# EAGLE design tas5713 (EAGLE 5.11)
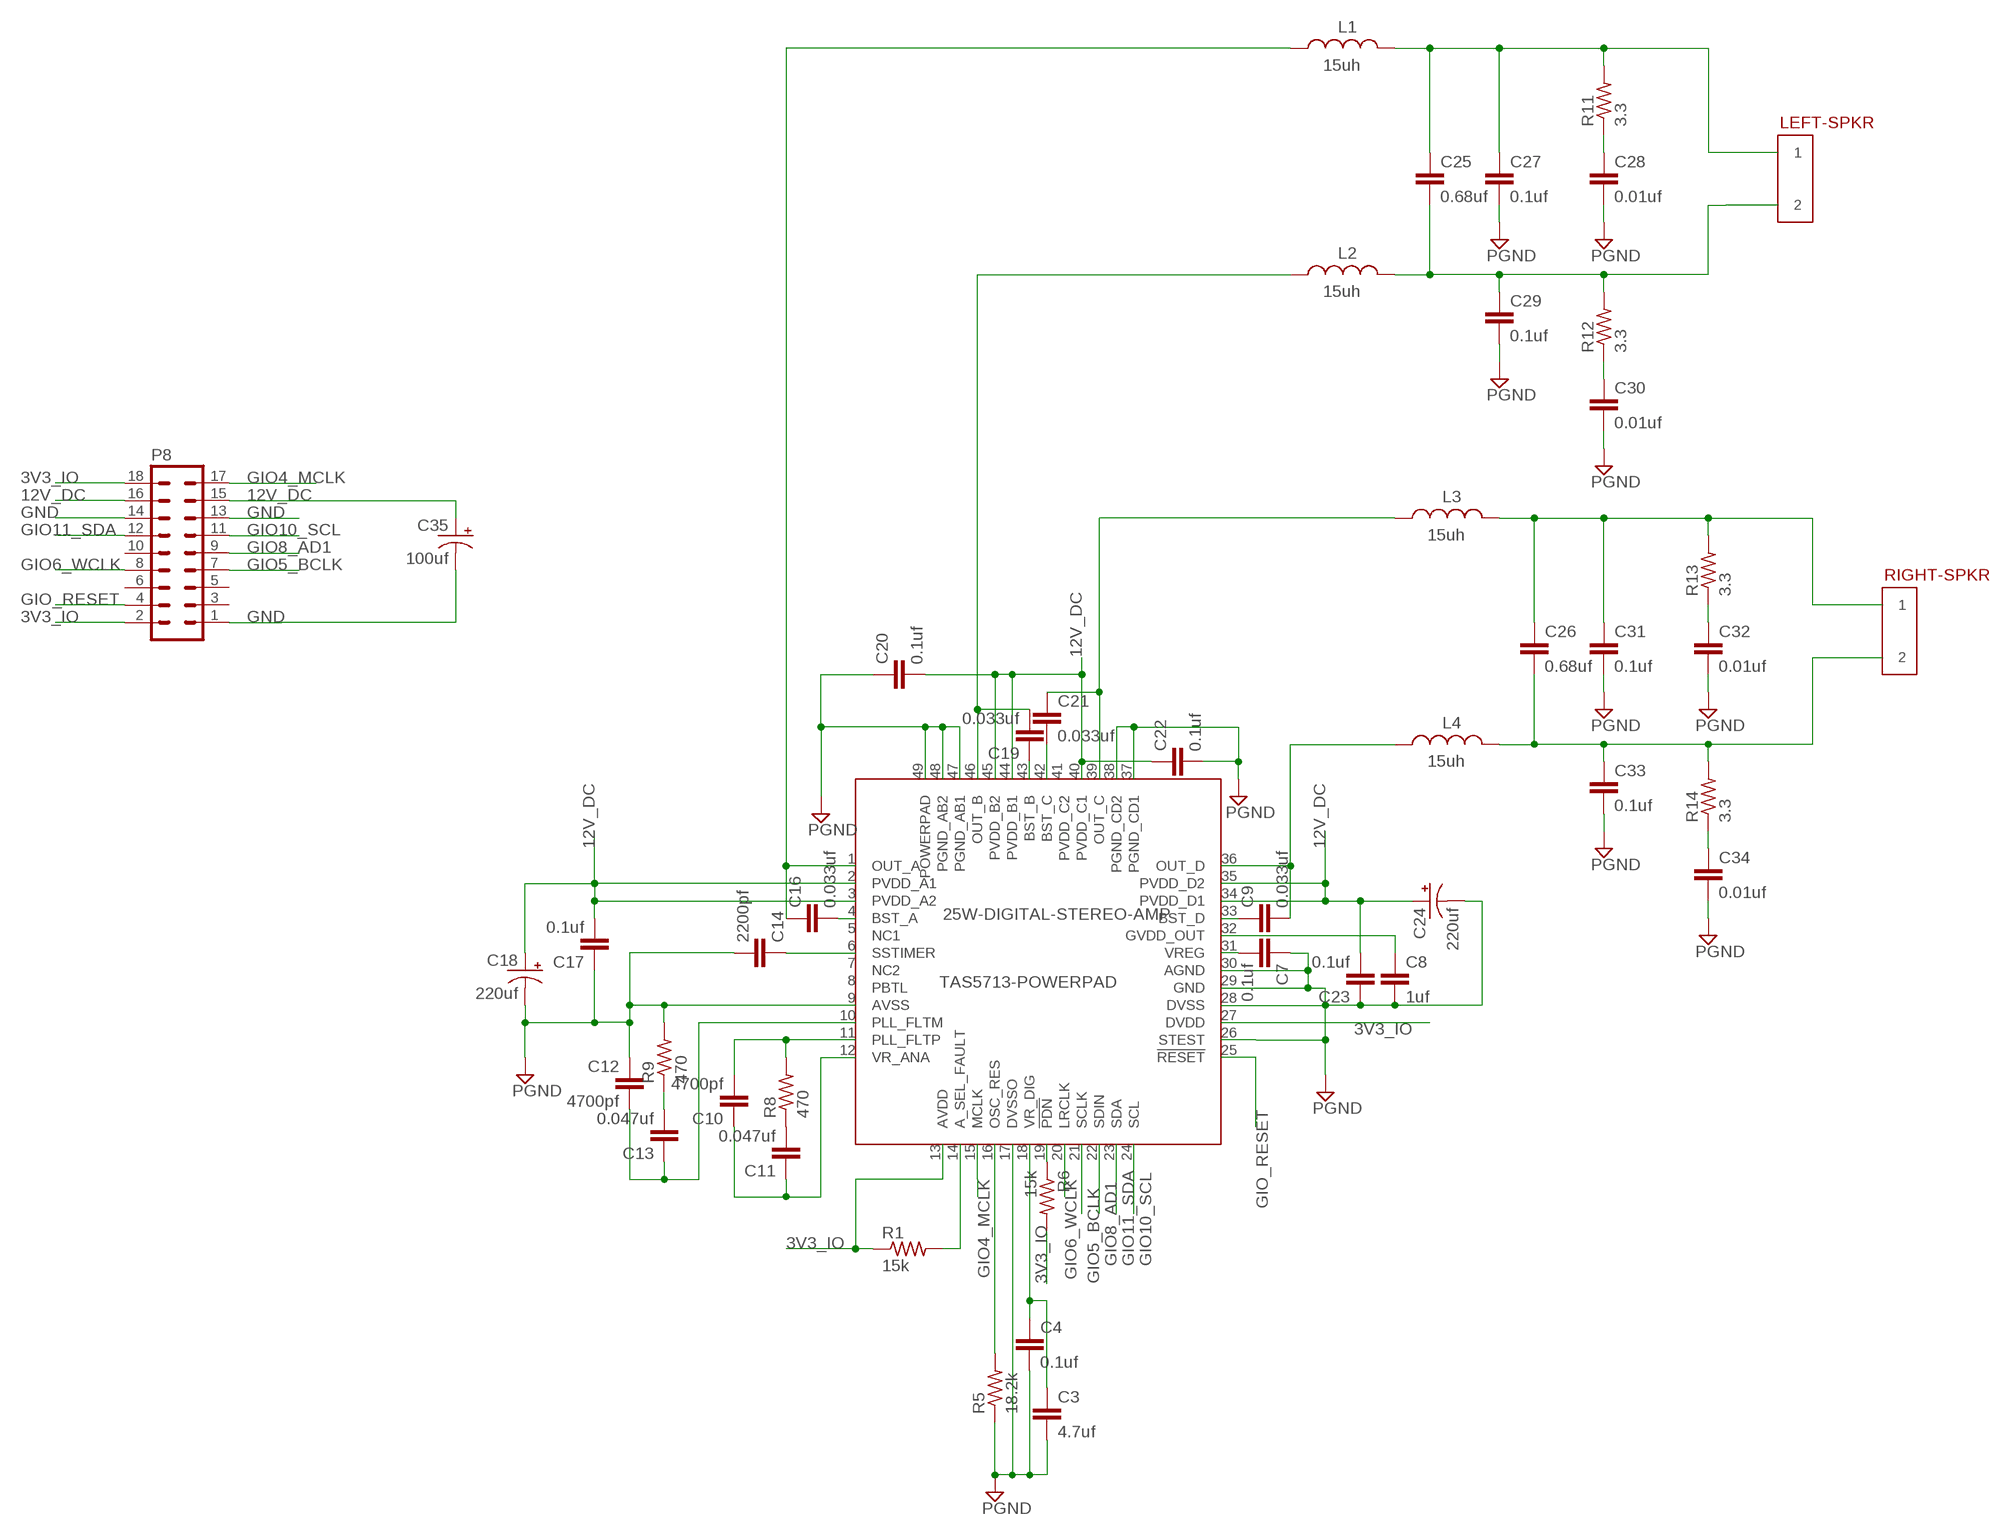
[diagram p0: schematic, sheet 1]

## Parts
25W-DIGITAL-STEREO-AMP  TAS5713-POWERPAD  [SCHMARTBOARD-VQFN48-POWERPAD]
C3  4.7uf  C-EUC1206  [C1206]
C4  0.1uf  C-EUC1206  [C1206]
C7  0.1uf  C-EUC1206  [C1206]
C8  1uf  C-EUC1206  [C1206]
C9  0.033uf  C-EUC1206  [C1206]
C10  4700pf  C-EUC1206  [C1206]
C11  0.047uf  C-EUC1206  [C1206]
C12  4700pf  C-EUC1206  [C1206]
C13  0.047uf  C-EUC1206  [C1206]
C14  2200pf  C-EUC1206  [C1206]
C16  0.033uf  C-EUC1206  [C1206]
C17  0.1uf  C-EUC1206  [C1206]
C18  220uf  CPOL-US175TMP-0808  [175TMP-0808]
C19  0.033uf  C-EUC1206  [C1206]
C20  0.1uf  C-EUC1206  [C1206]
C21  0.033uf  C-EUC1206  [C1206]
C22  0.1uf  C-EUC1206  [C1206]
C23  0.1uf  C-EUC1206  [C1206]
C24  220uf  CPOL-US175TMP-0808  [175TMP-0808]
C25  0.68uf  C-EUC1206  [C1206]
C26  0.68uf  C-EUC1206  [C1206]
C27  0.1uf  C-EUC1206  [C1206]
C28  0.01uf  C-EUC1206  [C1206]
C29  0.1uf  C-EUC1206  [C1206]
C30  0.01uf  C-EUC1206  [C1206]
C31  0.1uf  C-EUC1206  [C1206]
C32  0.01uf  C-EUC1206  [C1206]
C33  0.1uf  C-EUC1206  [C1206]
C34  0.01uf  C-EUC1206  [C1206]
C35  100uf  CPOL-US175TMP-0808  [175TMP-0808]
L1  15uh  INDUCTOR-ABRACON-1306S  [INDUCTOR-ABRACON-1306S]
L2  15uh  INDUCTOR-ABRACON-1306S  [INDUCTOR-ABRACON-1306S]
L3  15uh  INDUCTOR-ABRACON-1306S  [INDUCTOR-ABRACON-1306S]
L4  15uh  INDUCTOR-ABRACON-1306S  [INDUCTOR-ABRACON-1306S]
LEFT-SPKR  SCREW-CLAMP-1.5  [SCREW-CLAMP-1.5]
P8  MA09-2  [MA09-2]
R1  15k  R-US_R1206  [R1206]
R5  18.2k  R-US_R1206  [R1206]
R6  15k  R-US_R1206  [R1206]
R8  470  R-US_R1206  [R1206]
R9  470  R-US_R1206  [R1206]
R11  3.3  R-US_R1206  [R1206]
R12  3.3  R-US_R1206  [R1206]
R13  3.3  R-US_R1206  [R1206]
R14  3.3  R-US_R1206  [R1206]
RIGHT-SPKR  SCREW-CLAMP-1.5  [SCREW-CLAMP-1.5]

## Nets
3V3_IO: 25W-DIGITAL-STEREO-AMP.13(AVDD) 25W-DIGITAL-STEREO-AMP.27(DVDD) P8.2 P8.18 R1.1 R6.2
12V_DC: 25W-DIGITAL-STEREO-AMP.2(PVDD_A1) 25W-DIGITAL-STEREO-AMP.3(PVDD_A2) 25W-DIGITAL-STEREO-AMP.34(PVDD_D1) 25W-DIGITAL-STEREO-AMP.35(PVDD_D2) 25W-DIGITAL-STEREO-AMP.40(PVDD_C1) 25W-DIGITAL-STEREO-AMP.44(PVDD_B1) 25W-DIGITAL-STEREO-AMP.45(PVDD_B2) C17.2 C18.+ C20.2 C22.1 C23.2 C24.+ C35.+ P8.15 P8.16
GIO4_MCLK: 25W-DIGITAL-STEREO-AMP.15(MCLK) P8.17
GIO5_BCLK: 25W-DIGITAL-STEREO-AMP.21(SCLK) P8.7
GIO6_WCLK: 25W-DIGITAL-STEREO-AMP.20(LRCLK) P8.8
GIO8_AD1: 25W-DIGITAL-STEREO-AMP.22(SDIN) P8.9
GIO10_SCL: 25W-DIGITAL-STEREO-AMP.24(SCL) P8.11
GIO11_SDA: 25W-DIGITAL-STEREO-AMP.23(SDA) P8.12
GIO_RESET: 25W-DIGITAL-STEREO-AMP.25(!RESET) P8.4
GND: 25W-DIGITAL-STEREO-AMP.9(AVSS) 25W-DIGITAL-STEREO-AMP.17(DVSSO) 25W-DIGITAL-STEREO-AMP.26(STEST) 25W-DIGITAL-STEREO-AMP.28(DVSS) 25W-DIGITAL-STEREO-AMP.29(GND) 25W-DIGITAL-STEREO-AMP.30(AGND) 25W-DIGITAL-STEREO-AMP.37(PGND_CD1) 25W-DIGITAL-STEREO-AMP.38(PGND_CD2) 25W-DIGITAL-STEREO-AMP.47(PGND_AB1) 25W-DIGITAL-STEREO-AMP.48(PGND_AB2) 25W-DIGITAL-STEREO-AMP.49(POWERPAD) C3.2 C4.2 C7.1 C8.2 C12.1 C14.2 C17.1 C18.- C20.1 C22.2 C23.1 C24.- C27.2 C28.2 C29.2 C30.2 C31.2 C32.2 C33.2 C34.2 C35.- P8.1 P8.13 P8.14 R5.1 R9.2 ; supply symbol labelled PGND
N$1: 25W-DIGITAL-STEREO-AMP.4(BST_A) C16.2
N$2: 25W-DIGITAL-STEREO-AMP.1(OUT_A) C16.1 L1.1
N$3: 25W-DIGITAL-STEREO-AMP.43(BST_B) C19.1
N$4: 25W-DIGITAL-STEREO-AMP.46(OUT_B) C19.2 L2.1
N$5: 25W-DIGITAL-STEREO-AMP.42(BST_C) C21.2
N$6: 25W-DIGITAL-STEREO-AMP.14(A_SEL_FAULT) R1.2
N$7: 25W-DIGITAL-STEREO-AMP.33(BST_D) C9.1
N$8: 25W-DIGITAL-STEREO-AMP.36(OUT_D) C9.2 L4.1
N$9: 25W-DIGITAL-STEREO-AMP.31(VREG) C7.2
N$10: 25W-DIGITAL-STEREO-AMP.32(GVDD_OUT) C8.1
N$11: 25W-DIGITAL-STEREO-AMP.6(SSTIMER) C14.1
N$12: C28.1 R11.1
N$13: C25.2 C29.1 L2.2 LEFT-SPKR.2 R12.2
N$14: C30.1 R12.1
N$15: 25W-DIGITAL-STEREO-AMP.39(OUT_C) C21.1 L3.1
N$16: 25W-DIGITAL-STEREO-AMP.18(VR_DIG) C3.1 C4.1
N$17: 25W-DIGITAL-STEREO-AMP.16(OSC_RES) R5.2
N$18: C26.1 C31.1 L3.2 R13.2 RIGHT-SPKR.1
N$19: C25.1 C27.1 L1.2 LEFT-SPKR.1 R11.2
N$20: C32.1 R13.1
N$21: C26.2 C33.1 L4.2 R14.2 RIGHT-SPKR.2
N$22: C34.1 R14.1
N$23: 25W-DIGITAL-STEREO-AMP.19(!PDN) R6.1
N$24: 25W-DIGITAL-STEREO-AMP.10(PLL_FLTM) C12.2 C13.1
N$25: 25W-DIGITAL-STEREO-AMP.11(PLL_FLTP) C10.2 R8.2
N$26: 25W-DIGITAL-STEREO-AMP.12(VR_ANA) C10.1 C11.1
N$27: C11.2 R8.1
N$28: C13.2 R9.1
Unconnected: 25W-DIGITAL-STEREO-AMP.5(NC1) 25W-DIGITAL-STEREO-AMP.7(NC2) 25W-DIGITAL-STEREO-AMP.8(PBTL) 25W-DIGITAL-STEREO-AMP.41(PVDD_C2) P8.3 P8.5 P8.6 P8.10

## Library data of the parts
25W-DIGITAL-STEREO-AMP = trl:TAS5713-POWERPAD
C3 C4 C7-C14 C16 C17 C19-C23 C25-C34 = rcl:C-EU: CAPACITOR, European symbol
C18 C24 C35 = resistor:CPOL-US: POLARIZED CAPACITOR, American symbol
L1-L4 = trl:INDUCTOR-ABRACON-1306S
LEFT-SPKR RIGHT-SPKR = trl:SCREW-CLAMP-1.5
P8 = con-lstb:MA09-2: PIN HEADER
R1 R5 R6 R8 R9 R11-R14 = resistor:R-US_: RESISTOR, American symbol

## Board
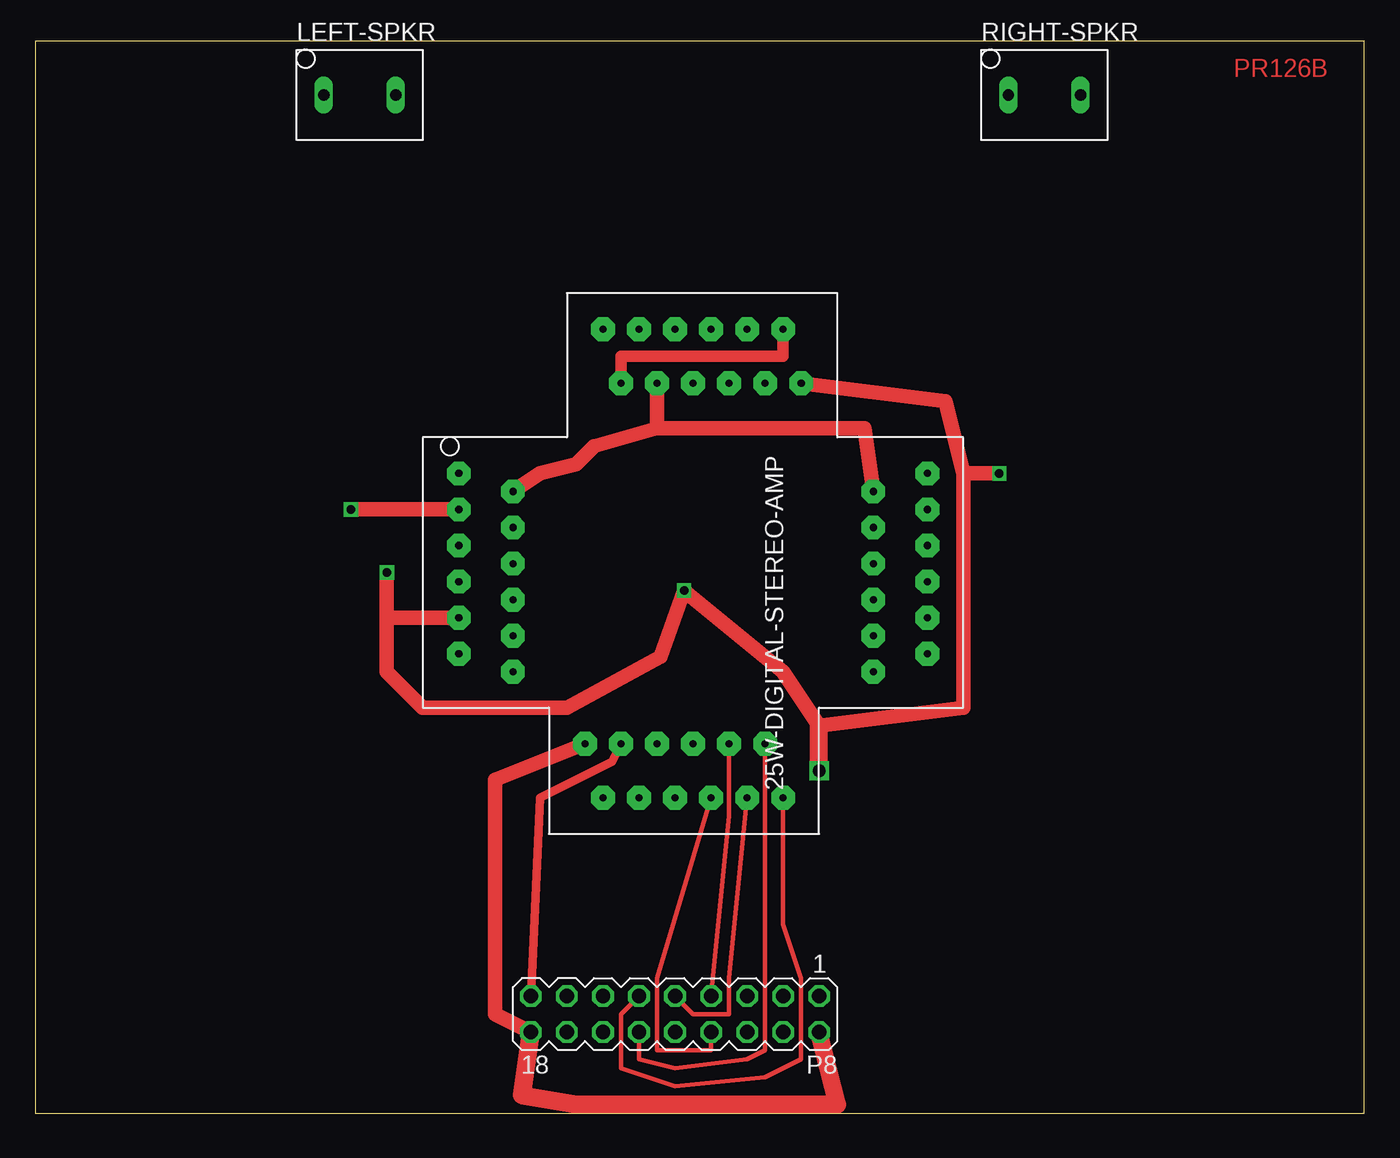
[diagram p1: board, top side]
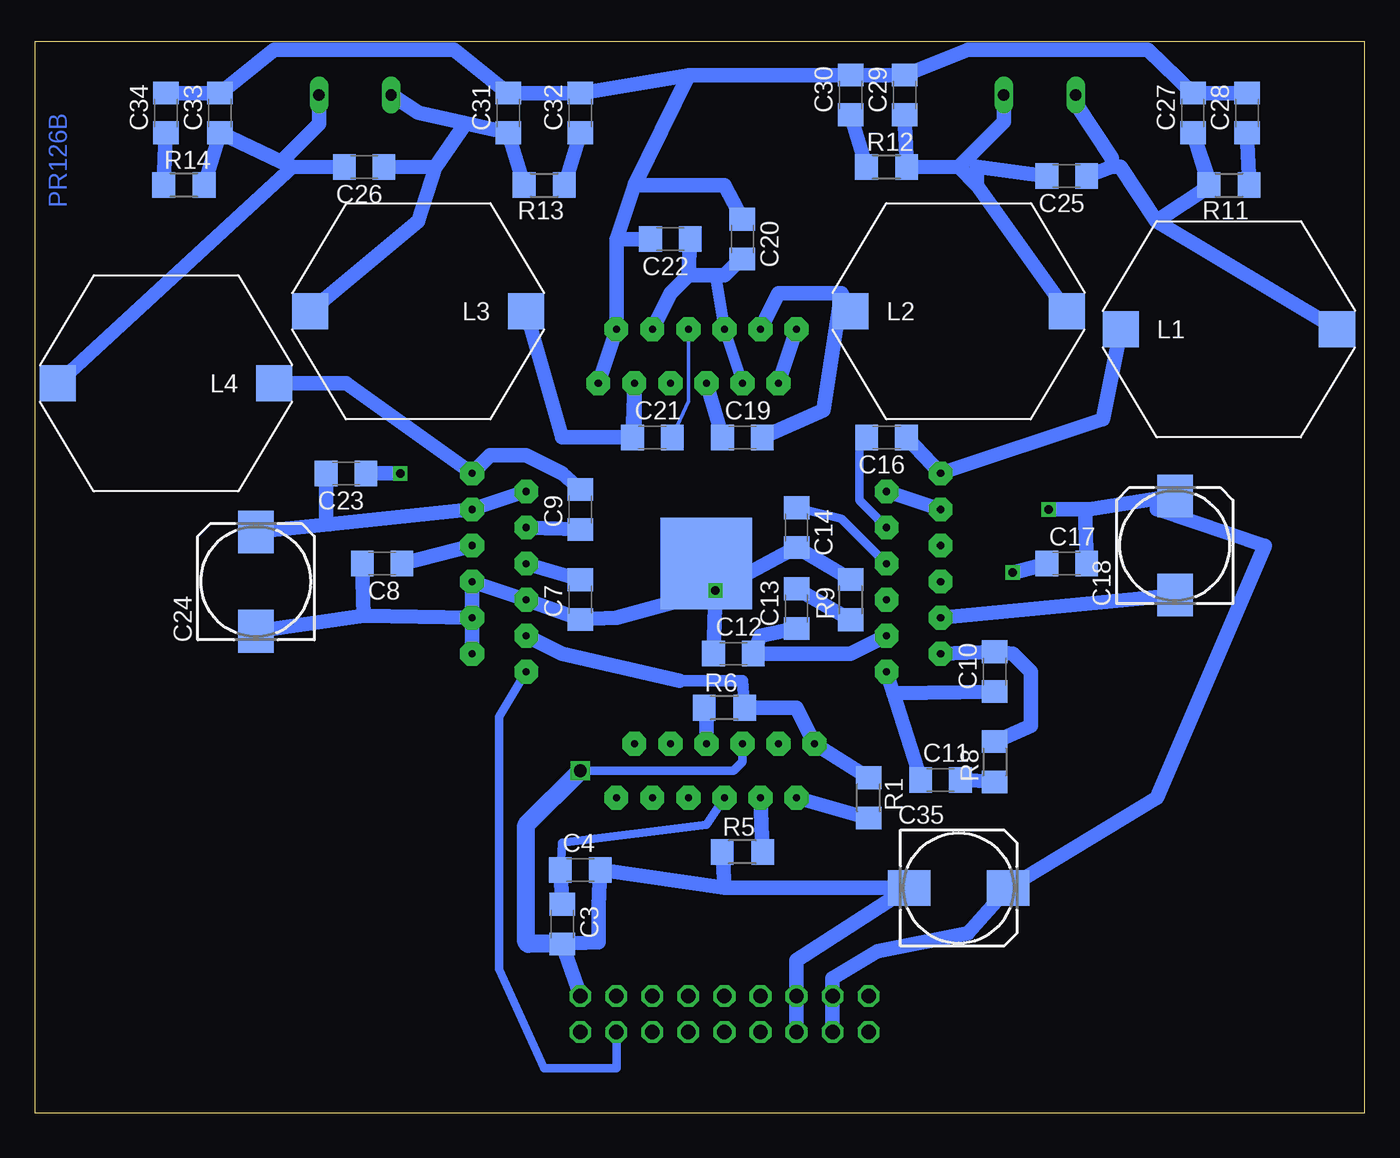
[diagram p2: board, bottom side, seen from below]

Size 93.65 x 75.56 mm. Coordinates in mm from the lower left corner, seen from the top.
Outline: 0,0 93.65,0 93.65,75.56 0,75.56 0,0
Copper layers (1*16): Top 0.035mm / dielectric 1.5mm / Bottom 0.035mm
Design rules "default": minimum track width 10mil, minimum drill 24mil, track to track 8mil, track to pad 8mil, pad to pad 8mil, via to via 8mil, smd to smd 8mil, copper to edge 40mil, drill to drill 8mil, minimum pad ring 10mil, minimum via ring 8mil, stop-mask expansion 4mil, vias tented up to drill 0mil, thermal gap 10mil

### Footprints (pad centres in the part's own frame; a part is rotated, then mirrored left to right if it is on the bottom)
SCHMARTBOARD-VQFN48-POWERPAD = drill 0.5 pad 1.676 octagon: 1 -6.35,-16.51; 2 -5.08,-12.7; 3 -3.81,-16.51; 4 -2.54,-12.7; 5 -1.27,-16.51; 6 0,-12.7; 7 1.27,-16.51; 8 2.54,-12.7; 9 3.81,-16.51; 10 5.08,-12.7; 11 6.35,-16.51; 12 7.62,-12.7; 13 12.7,-7.62; 14 16.51,-6.35; 15 12.7,-5.08; 16 16.51,-3.81; 17 12.7,-2.54; 18 16.51,-1.27; 19 12.7,0; 20 16.51,1.27; 21 12.7,2.54; 22 16.51,3.81; 23 12.7,5.08; 24 16.51,6.35; 25 7.62,12.7; 26 6.35,16.51; 27 5.08,12.7; 28 3.81,16.51; 29 2.54,12.7; 30 1.27,16.51; 31 0,12.7; 32 -1.27,16.51; 33 -2.54,12.7; 34 -3.81,16.51; 35 -5.08,12.7; 36 -6.35,16.51; 37 -12.7,7.62; 38 -16.51,6.35; 39 -12.7,5.08; 40 -16.51,3.81; 41 -12.7,2.54; 42 -16.51,1.27; 43 -12.7,0; 44 -16.51,-1.27; 45 -12.7,-2.54; 46 -16.51,-3.81; 47 -12.7,-5.08; 48 -16.51,-6.35 | smd 6.452 x 6.452 bottom: 49 0,0
C1206 = smd 1.6 x 1.8: 1 -1.4,0; 2 1.4,0
175TMP-0808 = smd 3 x 2.5: + 3.5,0; - -3.5,0
INDUCTOR-ABRACON-1306S = smd 2.54 x 2.54: 1 0,0; 2 15.24,0
SCREW-CLAMP-1.5 = drill 0.8 long: 1 -1.27,0; 2 3.81,0
MA09-2 = drill 1.016 octagon: 1 -10.16,-1.27; 2 -10.16,1.27; 3 -7.62,-1.27; 4 -7.62,1.27; 5 -5.08,-1.27; 6 -5.08,1.27; 7 -2.54,-1.27; 8 -2.54,1.27; 9 0,-1.27; 10 0,1.27; 11 2.54,-1.27; 12 2.54,1.27; 13 5.08,-1.27; 14 5.08,1.27; 15 7.62,-1.27; 16 7.62,1.27; 17 10.16,-1.27; 18 10.16,1.27
R1206 = smd 1.6 x 1.803: 1 -1.422,0; 2 1.422,0

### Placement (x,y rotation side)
25W-DIGITAL-STEREO-AMP  46.35,38.73 270 top
C3  56.52,13.34 270 bottom
C4  55.24,17.14 0 bottom
C7  55.24,36.2 90 bottom
C8  69.22,38.73 180 bottom
C9  55.24,42.55 90 bottom
C10  26.04,31.11 90 bottom
C11  29.84,23.5 0 bottom
C12  44.45,32.38 0 bottom
C13  40.01,35.56 90 bottom
C14  40.01,41.27 270 bottom
C16  33.66,47.62 180 bottom
C17  20.95,38.73 0 bottom
C18  13.34,40.01 90 bottom
C19  43.81,47.62 0 bottom
C20  43.81,61.59 270 bottom
C21  50.16,47.62 0 bottom
C22  48.9,61.59 180 bottom
C23  71.75,45.09 180 bottom
C24  78.11,37.47 90 bottom
C25  20.95,66.04 180 bottom
C26  70.48,66.67 180 bottom
C27  12.06,70.48 90 bottom
C28  8.26,70.48 90 bottom
C29  32.38,71.75 90 bottom
C30  36.2,71.75 90 bottom
C31  60.33,70.48 90 bottom
C32  55.24,70.48 90 bottom
C33  80.64,70.48 90 bottom
C34  84.45,70.48 90 bottom
C35  28.57,15.88 0 bottom
L1  17.14,55.24 0 bottom
L2  36.2,56.52 0 bottom
L3  59.05,56.52 180 bottom
L4  76.83,51.44 180 bottom
LEFT-SPKR  21.59,71.75 0 top
P8  45.09,6.99 180 top
R1  34.92,22.23 270 bottom
R5  43.81,18.41 0 bottom
R6  45.09,28.57 0 bottom
R8  26.04,24.77 90 bottom
R9  36.2,36.2 90 bottom
R11  9.53,65.41 180 bottom
R12  33.66,66.67 0 bottom
R13  57.78,65.41 180 bottom
R14  83.19,65.41 0 bottom
RIGHT-SPKR  69.85,71.75 0 top

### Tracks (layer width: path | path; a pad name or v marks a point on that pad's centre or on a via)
3V3_IO
  Top 1.016: P8.18 32.38,6.99 32.38,23.5 25W-DIGITAL-STEREO-AMP.13
  Top 1.27: P8.2 56.52,0.64 38.1,0.64 34.29,1.27 P8.18
  Bottom 0.813: R6.2 43.81,30.48 48.26,30.48
  Bottom 1.016: 48.26,30.48 56.52,32.38 25W-DIGITAL-STEREO-AMP.27 | R1.1 25W-DIGITAL-STEREO-AMP.13 40.01,28.57 R6.2
12V_DC  (via drill 0.6)
  Top 1.016: 43.81,48.26 58.42,48.26 25W-DIGITAL-STEREO-AMP.35 | 25W-DIGITAL-STEREO-AMP.2 35.56,45.09 38.1,45.72 39.37,46.99 43.81,48.26 | v22.23,42.55 25W-DIGITAL-STEREO-AMP.3 | 43.81,48.26 25W-DIGITAL-STEREO-AMP.45
  Bottom 0.813: 25W-DIGITAL-STEREO-AMP.45 25W-DIGITAL-STEREO-AMP.44 45.72,59.05
  Bottom 1.016: 72.92,41.5 25W-DIGITAL-STEREO-AMP.34 25W-DIGITAL-STEREO-AMP.35 | 72.92,41.5 C24.+ | P8.16 P8.15 37.47,9.53 34.29,11.43 27.94,12.7 C35.+ 14.61,22.23 6.99,40.01 14.61,42.55 C18.+ 19.38,42.55 19.68,42.55 | 25W-DIGITAL-STEREO-AMP.3 25W-DIGITAL-STEREO-AMP.2 | 47.62,59.05 48.9,57.78 25W-DIGITAL-STEREO-AMP.40 | 47.62,59.05 45.72,59.05 45.09,59.05 43.95,60.2 C20.2 | 19.68,42.55 v22.23,42.55 | C23.2 73.16,41.74 72.92,41.5 | 19.68,42.55 C17.2 | 47.62,59.05 C22.1
GIO4_MCLK
  Top 0.61: P8.17 35.56,22.23 40.64,24.77 25W-DIGITAL-STEREO-AMP.15
GIO5_BCLK
  Top 0.305: P8.7 48.9,20.95 25W-DIGITAL-STEREO-AMP.21
GIO6_WCLK
  Top 0.305: P8.8 47.62,4.45 43.81,4.45 43.81,9.53 25W-DIGITAL-STEREO-AMP.20
GIO8_AD1
  Top 0.305: 25W-DIGITAL-STEREO-AMP.22 48.9,9.53 48.9,8.26 48.9,6.99 46.35,6.99 P8.9
GIO10_SCL
  Top 0.305: 25W-DIGITAL-STEREO-AMP.24 52.7,13.34 53.98,9.53 53.98,3.81 51.44,2.54 45.09,1.91 41.27,3.17 41.27,6.99 P8.11
GIO11_SDA
  Top 0.305: 25W-DIGITAL-STEREO-AMP.23 51.44,5.71 51.44,4.45 50.16,3.81 45.09,3.17 42.55,3.81 P8.12
GIO_RESET
  Bottom 0.61: P8.4 52.7,3.17 57.78,3.17 60.96,10.16 60.96,27.94 25W-DIGITAL-STEREO-AMP.25
GND  (via drill 0.6, 0.9)
  Top 0.813: 25W-DIGITAL-STEREO-AMP.47 41.27,53.34 52.7,53.34 25W-DIGITAL-STEREO-AMP.38
  Top 1.016: 25W-DIGITAL-STEREO-AMP.37 64.14,50.16 65.41,45.09 | 65.41,45.09 65.41,28.57 55.24,27.3 52.7,31.11 v45.72,36.83 44.05,32.17 37.47,28.57 27.3,28.57 24.77,31.11 24.77,34.92 | 65.41,45.09 v67.94,45.09 | 24.77,34.92 25W-DIGITAL-STEREO-AMP.9 | 24.77,34.92 v24.77,38.1
  Top 1.27: v55.24,24.13 55.24,27.3
  Bottom 0.61: 25W-DIGITAL-STEREO-AMP.17 43.81,24.77 44.45,24.13 v55.24,24.13
  Bottom 1.016: C28.2 C27.2 15.24,74.93 27.94,74.93 C29.2 C30.2 47.62,73.16 | C34.2 C33.2 76.83,74.93 64.14,74.93 C31.2 C32.2 47.62,73.16 | 52.7,61.59 25W-DIGITAL-STEREO-AMP.38 25W-DIGITAL-STEREO-AMP.37 | 52.7,61.59 51.44,65.41 | 51.44,65.41 47.62,73.16 | 25W-DIGITAL-STEREO-AMP.47 25W-DIGITAL-STEREO-AMP.48 | 25W-DIGITAL-STEREO-AMP.28 70.52,35.06 | 70.52,35.06 C24.- | 70.52,35.06 C8.2 | 25W-DIGITAL-STEREO-AMP.28 25W-DIGITAL-STEREO-AMP.30 25W-DIGITAL-STEREO-AMP.29 C7.1 52.7,34.92 v45.72,36.83 | 25W-DIGITAL-STEREO-AMP.28 25W-DIGITAL-STEREO-AMP.26 | v45.72,36.83 C14.2 R9.2 | P8.14 P8.13 40.01,10.79 C35.- 45.09,15.88 | P8.1 C3.2 53.98,12.06 53.98,14.61 C4.2 45.09,15.88 | 25W-DIGITAL-STEREO-AMP.9 C18.- | 45.09,15.88 R5.1 | 52.7,61.59 C22.2 | 51.44,65.41 45.09,65.41 C20.1 | v67.94,45.09 C23.1 | v24.77,38.1 C17.1 | v45.72,36.83 C12.1 | 25W-DIGITAL-STEREO-AMP.49 46.35,37.47 v45.72,36.83
  Bottom 1.27: C3.2 58.92,11.94 59.05,12.06 59.05,20.32 v55.24,24.13
N$1
  Bottom 0.61: 25W-DIGITAL-STEREO-AMP.4 34.92,42.55 35.56,43.18 35.56,47.62 C16.2
N$2
  Bottom 1.016: L1.1 18.41,48.9 25W-DIGITAL-STEREO-AMP.1 C16.1
N$3
  Bottom 1.016: C19.1 25W-DIGITAL-STEREO-AMP.43
N$4
  Bottom 1.016: 36.83,57.78 L2.1 | 36.83,57.78 41.27,57.78 25W-DIGITAL-STEREO-AMP.46 | C19.2 38.1,49.53 36.83,57.78
N$5
  Bottom 0.254: C21.2 47.62,50.16 25W-DIGITAL-STEREO-AMP.42
N$6
  Bottom 1.016: R1.2 25W-DIGITAL-STEREO-AMP.14
N$7
  Bottom 1.016: 25W-DIGITAL-STEREO-AMP.33 C9.1
N$8
  Bottom 1.016: L4.1 71.75,51.44 25W-DIGITAL-STEREO-AMP.36 61.59,46.35 59.05,46.35 56.52,45.09 C9.2
N$9
  Bottom 1.016: 25W-DIGITAL-STEREO-AMP.31 C7.2
N$10
  Bottom 1.016: 25W-DIGITAL-STEREO-AMP.32 C8.1
N$11
  Bottom 0.61: 25W-DIGITAL-STEREO-AMP.6 35.56,40.64 36.83,41.91 C14.1
N$12
  Bottom 1.016: R11.1 C28.1
N$13
  Bottom 1.016: 27.29,65.41 27.28,66.69 C25.2 | L2.2 27.29,65.41 | C29.1 R12.2 28.56,66.71 | 27.29,65.41 28.56,66.71 | LEFT-SPKR.2 25.4,69.87 28.56,66.71
N$14
  Bottom 1.016: R12.1 C30.1
N$15
  Bottom 1.016: C21.1 25W-DIGITAL-STEREO-AMP.39 51.44,47.62 56.52,47.62 L3.1
N$16
  Bottom 0.61: C4.1 56.52,19.05 46.35,20.32 25W-DIGITAL-STEREO-AMP.18
  Bottom 1.016: C4.1 C3.1
N$17
  Bottom 1.016: R5.2 25W-DIGITAL-STEREO-AMP.16
N$18
  Bottom 1.016: L3.2 66.67,62.87 65.44,66.69 | 65.44,66.69 C26.1 | R13.2 C31.1 63.34,69.74 | 63.34,69.74 65.44,66.69 | RIGHT-SPKR.1 66.63,70.48 63.34,69.74
N$19
  Bottom 1.016: R11.2 C27.1 10.79,65.41 14.62,62.87 | L1.2 14.62,62.87 | 14.62,62.87 17.17,66.69 17.78,66.68 | 17.78,66.68 C25.1 | LEFT-SPKR.1 20.32,71.12 17.78,67.31 17.78,66.69 17.78,66.68
N$20
  Bottom 1.016: R13.1 C32.1
N$21
  Bottom 1.016: 75.54,66.69 L4.2 | C26.2 75.54,66.69 | 75.54,66.69 76.32,67.05 | 76.32,67.05 C33.1 R14.2 | RIGHT-SPKR.2 73.66,69.71 76.32,67.05
N$22
  Bottom 1.016: R14.1 C34.1
N$23
  Bottom 1.016: 25W-DIGITAL-STEREO-AMP.19 46.35,28.57 R6.1
N$24
  Bottom 1.016: C13.1 42.55,33.66 C12.2 36.2,32.38 25W-DIGITAL-STEREO-AMP.10
N$25
  Bottom 1.016: R8.2 23.5,27.3 23.5,31.11 24.77,32.38 C10.2 25W-DIGITAL-STEREO-AMP.11
N$26
  Bottom 1.016: C11.1 33.17,29.59 | 33.17,29.59 25W-DIGITAL-STEREO-AMP.12 | 33.17,29.59 C10.1
N$27
  Bottom 1.016: R8.1 C11.2
N$28
  Bottom 1.016: C13.2 R9.1

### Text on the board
Top: PR126B
Bottom: PR126B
